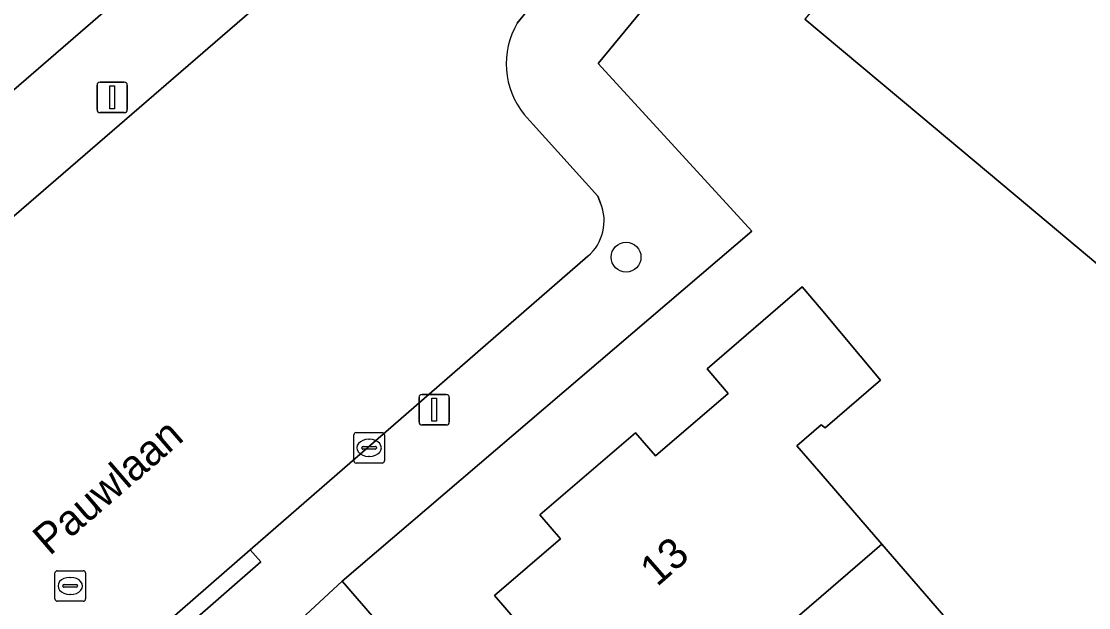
# Model space of a CAD drawing. Extents: x 161772 to 163126, y 383092 to 383917.
# Drawn here: x 162473.8 to 162508.77, y 383529.18 to 383548.4 of the extents above; entities that cross this region are included whole.
import ezdxf

# ---------------------------------------------------------------- set-up
doc = ezdxf.new("R2010")
doc.units = 0
for name, color, linetype in [('IMGEO_Boom', 7, 'Continuous'), ('IMGEO_Erf', 7, 'Continuous'), ('IMGEO_Kolk', 7, 'Continuous'), ('IMGEO_Lichtmast', 7, 'Continuous'), ('IMGEO_Openbare_ruimte_label', 7, 'Continuous'), ('IMGEO_Pand', 7, 'Continuous'), ('IMGEO_Pand_nummerreeks', 7, 'Continuous'), ('IMGEO_Rijbaan_lokaal_open', 7, 'Continuous'), ('IMGEO_Rioolput', 7, 'Continuous'), ('IMGEO_Voetpad_open', 7, 'Continuous')]:
    doc.layers.add(name, color=color, linetype=linetype)

msp = doc.modelspace()

# ---------------------------------------------------------------- linework, layer by layer
at = {"layer": 'IMGEO_Boom'}
msp.add_circle((162493.612, 383540.669), 0.489, dxfattribs=at)
at = {"layer": 'IMGEO_Erf'}
for points in [[(162462.704, 383536.779), (162483.744, 383554.98), (162500, 383574.599), (162526.947, 383607.122), (162543.804, 383623.317), (162548.918, 383628.126), (162539.791, 383641.093), (162527.133, 383641.683), (162527.105, 383641.456), (162500, 383642.583), (162442.25, 383644.984), (162375.184, 383528.714), (162418.191, 383500), (162425.357, 383495.215)], [(162500, 383555.89), (162492.693, 383547.017), (162497.729, 383541.518), (162484.308, 383530.048), (162510.809, 383499.431)], [(162519.266, 383552.231), (162515.623, 383547.758), (162518.136, 383545.677), (162518.601, 383546.015), (162520.342, 383544.573), (162519.14, 383543.122), (162519.035, 383542.995), (162517.37, 383544.374), (162514.671, 383546.609), (162511.12, 383542.324), (162509.345, 383540.203), (162506.761, 383542.365), (162503.265, 383545.293), (162500, 383548.023), (162499.466, 383548.469)], [(162491.047, 383527.552), (162489.304, 383529.58), (162491.468, 383531.44), (162490.792, 383532.227), (162493.919, 383534.915), (162494.572, 383534.154), (162496.959, 383536.205), (162496.267, 383537.01), (162499.387, 383539.692), (162500, 383538.961), (162501.95, 383536.636), (162500.133, 383535.075), (162500, 383535.172), (162499.207, 383534.489), (162500, 383533.572), (162501.996, 383531.263), (162506.744, 383525.769)]]:
    msp.add_lwpolyline(points, dxfattribs=at)
at = {"layer": 'IMGEO_Kolk'}
for p, q in [((162484.692, 383533.993), (162484.692, 383534.845)), ((162484.767, 383534.919), (162485.619, 383534.919)), ((162485.18, 383534.699), (162485.205, 383534.699)), ((162485.693, 383534.845), (162485.693, 383533.993)), ((162484.951, 383534.413), (162484.951, 383534.425)), ((162485.389, 383534.376), (162484.991, 383534.376)), ((162484.994, 383534.462), (162485.392, 383534.462)), ((162485.435, 383534.425), (162485.435, 383534.413)), ((162485.619, 383533.919), (162484.767, 383533.919)), ((162485.203, 383534.139), (162485.178, 383534.139))]:
    msp.add_line(p, q, dxfattribs=at)
for points in [[(162484.692, 383533.993), (162484.692, 383534.845)], [(162484.767, 383534.919), (162485.619, 383534.919)], [(162485.693, 383534.845), (162485.693, 383533.993)], [(162485.619, 383533.919), (162484.767, 383533.919)]]:
    msp.add_lwpolyline(points, dxfattribs=at)
for centre, radius, start, end in [((162484.769, 383534.843), 0.0765, 91.552, 178.448), ((162484.769, 383534.843), 0.0765, 91.552, 178.448), ((162485.617, 383534.843), 0.0765, 1.552, 88.448), ((162485.617, 383534.843), 0.0765, 1.552, 88.448), ((162484.991, 383534.422), 0.0403, 85.8775, 175.7526), ((162484.988, 383534.412), 0.0366, 178.938, 274.7102), ((162485.392, 383534.419), 0.043, 264.8664, 352.4533), ((162485.396, 383534.424), 0.0386, 1.7309, 96.639), ((162484.769, 383533.995), 0.0765, 181.552, 268.448), ((162484.769, 383533.995), 0.0765, 181.552, 268.448), ((162485.617, 383533.995), 0.0765, 271.552, 358.448), ((162485.617, 383533.995), 0.0765, 271.552, 358.448)]:
    msp.add_arc(centre, radius, start, end, dxfattribs=at)
for centre, major_axis, ratio, start_param, end_param in [((162485.179, 383534.419), (-0.387, 0.002), 0.722429, 4.712389, 7.853982), ((162485.204, 383534.419), (-0.39, 0.002), 0.717154, 1.570796, 4.712389)]:
    msp.add_ellipse(centre, major_axis=major_axis, ratio=ratio, start_param=start_param, end_param=end_param, dxfattribs=at)
at = {"layer": 'IMGEO_Lichtmast'}
for p, q in [((162476.279, 383545.505), (162476.279, 383546.305)), ((162476.279, 383546.305), (162476.279, 383545.505)), ((162476.379, 383546.405), (162477.169, 383546.405)), ((162477.169, 383546.405), (162476.379, 383546.405)), ((162477.269, 383546.305), (162477.269, 383545.505)), ((162477.269, 383545.505), (162477.269, 383546.305)), ((162477.169, 383545.405), (162476.379, 383545.405)), ((162476.379, 383545.405), (162477.169, 383545.405)), ((162486.829, 383535.269), (162486.829, 383536.069)), ((162486.829, 383536.069), (162486.829, 383535.269)), ((162486.929, 383536.169), (162487.719, 383536.169)), ((162487.719, 383536.169), (162486.929, 383536.169)), ((162487.819, 383536.069), (162487.819, 383535.269)), ((162487.819, 383535.269), (162487.819, 383536.069)), ((162487.719, 383535.169), (162486.929, 383535.169)), ((162486.929, 383535.169), (162487.719, 383535.169))]:
    msp.add_line(p, q, dxfattribs=at)
for points in [[(162476.699, 383546.28), (162476.849, 383546.28), (162476.849, 383545.53), (162476.699, 383545.53), (162476.699, 383546.28)], [(162487.249, 383536.044), (162487.399, 383536.044), (162487.399, 383535.294), (162487.249, 383535.294), (162487.249, 383536.044)]]:
    msp.add_lwpolyline(points, dxfattribs=at)
for centre, start, end in [((162476.379, 383546.305), 90, 180), ((162476.379, 383546.305), 90, 180), ((162477.169, 383546.305), 0, 90), ((162477.169, 383546.305), 360, 90), ((162476.379, 383545.505), 180, 270), ((162476.379, 383545.505), 180, 270), ((162477.169, 383545.505), 270, 0), ((162477.169, 383545.505), 270, 0), ((162486.929, 383536.069), 90, 180), ((162486.929, 383536.069), 90, 180), ((162487.719, 383536.069), 0, 90), ((162487.719, 383536.069), 360, 90), ((162486.929, 383535.269), 180, 270), ((162486.929, 383535.269), 180, 270), ((162487.719, 383535.269), 270, 0), ((162487.719, 383535.269), 270, 0)]:
    msp.add_arc(centre, 0.1, start, end, dxfattribs=at)
at = {"layer": 'IMGEO_Pand'}
for points in [[(162503.842, 383555.768), (162503.146, 383554.928), (162502.443, 383554.862), (162501.427, 383553.635), (162501.492, 383552.948), (162500, 383551.142), (162499.194, 383550.167), (162500, 383549.474), (162500.175, 383549.323), (162500, 383549.112), (162499.466, 383548.469), (162500, 383548.023), (162503.265, 383545.293), (162506.761, 383542.365), (162509.345, 383540.203), (162511.12, 383542.324), (162514.671, 383546.609), (162514.883, 383546.865), (162513.455, 383548.049)], [(162493.638, 383524.064), (162500, 383529.544), (162501.996, 383531.263), (162500, 383533.572), (162499.207, 383534.489), (162500, 383535.172), (162500.133, 383535.075), (162501.95, 383536.636), (162500, 383538.961), (162499.387, 383539.692), (162496.267, 383537.01), (162496.959, 383536.205), (162494.572, 383534.154), (162493.919, 383534.915), (162490.792, 383532.227), (162491.468, 383531.44), (162489.304, 383529.58), (162491.047, 383527.552), (162490.821, 383527.358), (162491.497, 383526.572), (162491.424, 383525.605), (162492.373, 383524.501), (162493.324, 383524.429)], [(162506.744, 383525.769), (162501.996, 383531.263), (162500, 383529.544), (162493.638, 383524.064), (162498.442, 383518.487), (162500, 383519.83), (162506.619, 383525.531)]]:
    msp.add_lwpolyline(points, close=True, dxfattribs=at)
at = {"layer": 'IMGEO_Rijbaan_lokaal_open'}
for points in [[(162490.049, 383548.342), (162490.534, 383548.934), (162485.735, 383552.822), (162484.483, 383551.467), (162468.577, 383537.721)], [(162492.779, 383542.442), (162492.686, 383542.671), (162490.572, 383545.015), (162490.273, 383545.344)], [(162475.321, 383525.871), (162481.301, 383531.073), (162492.362, 383540.697)]]:
    msp.add_lwpolyline(points, dxfattribs=at)
for centre, radius, start, end in [((162492.349, 383547.007), 2.66, 149.864, 218.682), ((162491.359, 383541.859), 1.535, 310.7908, 22.3295)]:
    msp.add_arc(centre, radius, start, end, dxfattribs=at)
at = {"layer": 'IMGEO_Rioolput'}
for p, q in [((162474.901, 383529.467), (162474.901, 383530.319)), ((162474.976, 383530.393), (162475.828, 383530.393)), ((162475.389, 383530.173), (162475.414, 383530.173)), ((162475.902, 383530.319), (162475.902, 383529.467)), ((162475.16, 383529.887), (162475.16, 383529.899)), ((162475.598, 383529.85), (162475.2, 383529.85)), ((162475.203, 383529.936), (162475.601, 383529.936)), ((162475.644, 383529.899), (162475.644, 383529.887)), ((162475.828, 383529.393), (162474.976, 383529.393)), ((162475.412, 383529.613), (162475.387, 383529.613))]:
    msp.add_line(p, q, dxfattribs=at)
for points in [[(162474.901, 383529.467), (162474.901, 383530.319)], [(162474.976, 383530.393), (162475.828, 383530.393)], [(162475.902, 383530.319), (162475.902, 383529.467)], [(162475.828, 383529.393), (162474.976, 383529.393)]]:
    msp.add_lwpolyline(points, dxfattribs=at)
for centre, radius, start, end in [((162474.978, 383530.317), 0.0765, 91.552, 178.448), ((162474.978, 383530.317), 0.0765, 91.552, 178.448), ((162475.826, 383530.317), 0.0765, 1.552, 88.448), ((162475.826, 383530.317), 0.0765, 1.552, 88.448), ((162475.2, 383529.896), 0.0403, 85.8775, 175.7526), ((162475.197, 383529.886), 0.0366, 178.938, 274.7102), ((162475.601, 383529.893), 0.043, 264.8664, 352.4533), ((162475.605, 383529.898), 0.0386, 1.7309, 96.639), ((162474.978, 383529.469), 0.0765, 181.552, 268.448), ((162474.978, 383529.469), 0.0765, 181.552, 268.448), ((162475.826, 383529.469), 0.0765, 271.552, 358.448), ((162475.826, 383529.469), 0.0765, 271.552, 358.448)]:
    msp.add_arc(centre, radius, start, end, dxfattribs=at)
for centre, major_axis, ratio, start_param, end_param in [((162475.388, 383529.893), (-0.387, 0.002), 0.722429, 4.712389, 7.853982), ((162475.413, 383529.893), (-0.39, 0.002), 0.717154, 1.570796, 4.712389)]:
    msp.add_ellipse(centre, major_axis=major_axis, ratio=ratio, start_param=start_param, end_param=end_param, dxfattribs=at)
at = {"layer": 'IMGEO_Voetpad_open'}
for points in [[(162549.66, 383629.858), (162548.918, 383628.126), (162543.804, 383623.317), (162526.947, 383607.122), (162500, 383574.599), (162483.744, 383554.98), (162462.704, 383536.779), (162467.807, 383530.859), (162432.045, 383500), (162426.613, 383495.312), (162428.778, 383494.029), (162435.72, 383500), (162437.045, 383501.14), (162437.192, 383501.282), (162438.691, 383502.574), (162438.438, 383502.865), (162441.394, 383505.425), (162441.654, 383505.126), (162443.112, 383506.379), (162469.395, 383528.971)], [(162468.577, 383537.721), (162484.483, 383551.467), (162485.735, 383552.822), (162487.591, 383555.051), (162488.243, 383555.841), (162487.915, 383556.108), (162490.371, 383559.116), (162490.713, 383558.838), (162499.96, 383570.06), (162503.132, 383574.038), (162507.749, 383579.508), (162511.095, 383583.664), (162510.859, 383583.859), (162513.286, 383586.801), (162513.52, 383586.607), (162520.458, 383594.506), (162527.435, 383602.384), (162532.418, 383607.776), (162537.203, 383612.786), (162540.103, 383615.776), (162538.984, 383617.258), (162540.462, 383618.813), (162542.308, 383616.755)], [(162497.729, 383541.518), (162492.693, 383547.017), (162500, 383555.89), (162501.518, 383557.733), (162510.666, 383568.842), (162518.786, 383578.702), (162525.907, 383586.964), (162533.89, 383595.873), (162539.703, 383602.034), (162537.488, 383604.096), (162530.565, 383596.403), (162527.89, 383593.519), (162528.327, 383593.13), (162525.868, 383590.36), (162525.402, 383590.777), (162521.297, 383586.253), (162517.639, 383581.965), (162512.205, 383575.261), (162506.576, 383568.47), (162499.866, 383560.331), (162492.315, 383551.109), (162490.534, 383548.934), (162490.049, 383548.342)], [(162490.273, 383545.344), (162490.572, 383545.015), (162492.686, 383542.671), (162492.779, 383542.442)], [(162475.569, 383521.813), (162477.588, 383524.09), (162482.084, 383527.984), (162484.308, 383530.048), (162497.729, 383541.518)], [(162492.362, 383540.697), (162481.301, 383531.073), (162481.643, 383530.681), (162475.674, 383525.466), (162475.321, 383525.871), (162467.06, 383518.683), (162445.287, 383500.025), (162441.857, 383497.02), (162441.094, 383496.401), (162443.732, 383494.748), (162449.833, 383500), (162474.854, 383521.793)], [(162515.75, 383493.665), (162510.938, 383499.282), (162510.809, 383499.431), (162484.308, 383530.048), (162482.084, 383527.984), (162482.473, 383527.536), (162509.259, 383496.545), (162509.608, 383496.81), (162512.227, 383493.778), (162511.902, 383493.48), (162520.618, 383483.371)]]:
    msp.add_lwpolyline(points, dxfattribs=at)
msp.add_lwpolyline([(162475.321, 383525.871), (162475.674, 383525.466), (162481.643, 383530.681), (162481.301, 383531.073)], close=True, dxfattribs=at)
for centre, radius, start, end in [((162492.349, 383547.007), 2.66, 149.864, 218.682), ((162491.359, 383541.859), 1.535, 310.7908, 22.3295)]:
    msp.add_arc(centre, radius, start, end, dxfattribs=at)

# ---------------------------------------------------------------- texts
at = {"layer": 'IMGEO_Openbare_ruimte_label'}
msp.add_text('Pauwlaan', height=1, rotation=40.7816, dxfattribs=at).set_placement((162474.725, 383530.86))
at = {"layer": 'IMGEO_Pand_nummerreeks'}
msp.add_text('13', height=1, rotation=41.165, dxfattribs=at).set_placement((162494.626, 383529.844))

doc.saveas('drawing.dxf')
